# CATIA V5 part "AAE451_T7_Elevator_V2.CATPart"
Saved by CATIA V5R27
Part number: Elevator
Bounding box of the stored display mesh (mm): x 0 to 69.698, y -12.436 to 0.05, z -344.945 to 344.945
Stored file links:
  W:\AAE 451\AAE451_T7_TailAssembly_V2\AAE451_T7_Elevator_V2.CATPart
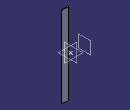
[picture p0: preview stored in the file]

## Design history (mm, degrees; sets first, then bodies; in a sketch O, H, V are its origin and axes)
Set1 "GeometryFromExcel"
  Point1: (1, 0.001, 0)
  Point2: (0.95, 0.0067, 0)
  Point3: (0.9, 0.0121, 0)
  Point4: (0.8, 0.0219, 0)
  Point5: (0.7, 0.0305, 0)
  Point6: (0.6, 0.038, 0)
  Point7: (0.5, 0.0441, 0)
  Point8: (0.4, 0.0484, 0)
  Point9: (0.3, 0.05, 0)
  Point10: (0.25, 0.0495, 0)
  Point11: (0.2, 0.0478, 0)
  Point12: (0.15, 0.0445, 0)
  Point13: (0.1, 0.039, 0)
  Point14: (0.075, 0.035, 0)
  Point15: (0.05, 0.0296, 0)
  Point16: (0.025, 0.0218, 0)
  Point17: (0.0125, 0.0158, 0)
  Point18: (0, 0, 0)
  Point19: (0.0125, -0.0158, 0)
  Point20: (0.025, -0.0218, 0)
  Point21: (0.05, -0.0296, 0)
  Point22: (0.075, -0.035, 0)
  Point23: (0.1, -0.039, 0)
  Point24: (0.15, -0.0445, 0)
  Point25: (0.2, -0.0478, 0)
  Point26: (0.25, -0.0495, 0)
  Point27: (0.3, -0.05, 0)
  Point28: (0.4, -0.0484, 0)
  Point29: (0.5, -0.0441, 0)
  Point30: (0.6, -0.038, 0)
  Point31: (0.7, -0.0305, 0)
  Point32: (0.8, -0.0219, 0)
  Point33: (0.9, -0.0121, 0)
  Point34: (0.95, -0.0067, 0)
  Point35: (1, -0.001, 0)
  Point36: (1, 0.001, 0)
  Point37: (0.95, 0.0067, 0)
  Point38: (0.9, 0.0121, 0)
  Point39: (0.8, 0.0219, 0)
  Point40: (0.7, 0.0305, 0)
  Point41: (0.6, 0.038, 0)
  Point42: (0.5, 0.0441, 0)
  Point43: (0.4, 0.0484, 0)
  Point44: (0.3, 0.05, 0)
  Point45: (0.25, 0.0495, 0)
  Point46: (0.2, 0.0478, 0)
  Point47: (0.15, 0.0445, 0)
  Point48: (0.1, 0.039, 0)
  Point49: (0.075, 0.035, 0)
  Point50: (0.05, 0.0296, 0)
  Point51: (0.025, 0.0218, 0)
  Point52: (0.0125, 0.0158, 0)
  Point53: (0, 0, 0)
  Point54: (0.0125, -0.0158, 0)
  Point55: (0.025, -0.0218, 0)
  Point56: (0.05, -0.0296, 0)
  Point57: (0.075, -0.035, 0)
  Point58: (0.1, -0.039, 0)
  Point59: (0.15, -0.0445, 0)
  Point60: (0.2, -0.0478, 0)
  Point61: (0.25, -0.0495, 0)
  Point62: (0.3, -0.05, 0)
  Point63: (0.4, -0.0484, 0)
  Point64: (0.5, -0.0441, 0)
  Point65: (0.6, -0.038, 0)
  Point66: (0.7, -0.0305, 0)
  Point67: (0.8, -0.0219, 0)
  Point68: (0.9, -0.0121, 0)
  Point69: (0.95, -0.0067, 0)
  Point70: (1, -0.001, 0)
  Curve1: Elements (Point36; Point37; Point38; Point39; Point40; Point41; Point42; Point43; Point44; Point45; Point46; Point47; Point48; Point49; Point50; Point51; Point52; Point53; Point54; Point55; Point56; Point57; Point58; Point59; Point60; Point61; Point62; Point63; Point64; Point65; Point66; Point67; Point68; Point69; Point70)
  Sketch1 on xy-plane, origin (0, 0, 0), H (1, 0, 0), V (0, 1, 0)
    projected curve E1 from edge of Curve1
    point P1 (1, 0.0011)
    line L1 (1, 0.0011) -> (1, -0.001)
    point P3 (1, 0.001)
    point P4 (1, -0.001)
    reference projected point E2 (1, 0.001) from Point1
    reference projected point E3 (1, -0.001) from Point35
    coincidence: P3 E2, P4 E3, P1 P3
Body1 (main body)
  Pad1: profile Sketch1, direction (0, 0, 1), length 1.5215, mirrored extent
  Scaling1: ToTransfor Pad1, Reference Point40, Ratio 230
  Plane1: type Offset, RefPlane yz-plane, Offset 120, reversed
  Sketch2 on xy-plane, origin (0, 0, 0), H (1, 0, 0), V (0, 1, 0)
    reference projected line E1 (69.6979, -7.2245) -> (69.698, -6.7499) from edge [face of Pad1 from Sketch1.L1 | end face of Pad1]
    line L1 (13.6994, -1.0636) -> (13.6965, -12.9194)
    projected curve E2 from edge [face of Pad1 from Sketch1.E1 | end face of Pad1]
    projected curve E3 from edge [face of Pad1 from Sketch1.E1 | end face of Pad1]
    distance E1 L1 = 56
  Pocket1: profile Sketch2, direction (0, 0, -1), through (limit type 3), opposite side through (limit type 3)
  Fillet1: radius 5, on edge [face of Pad1 from Sketch1.E1 | face of Pocket1 from Sketch2.L1]; edge [face of Pocket1 from Sketch2.L1 | face of Pad1 from Sketch1.E1]
  Sketch3 on zx-plane, origin (0, 0, 0), H (-1, 0, 0), V (0, 0, 1)
    line L1 (-135.4649, -344.945) -> (50.2623, -344.945)
    line L2 (50.2623, -344.945) -> (50.2623, -349.945)
    line L3 (50.2623, -349.945) -> (-135.4649, -349.945)
    line L4 (-135.4649, -349.945) -> (-135.4649, -344.945)
    line L5 (-146.4826, 349.945) -> (56.5582, 349.945)
    line L6 (56.5582, 349.945) -> (56.5582, 344.945)
    line L7 (56.5582, 344.945) -> (-146.4826, 344.945)
    line L8 (-146.4826, 344.945) -> (-146.4826, 349.945)
    reference projected line E1 (-69.7, 349.945) -> (160.3, 349.945) from edge [face of Pad1 from Sketch1.E1 | end face of Pad1]
    reference projected line E2 (-69.7, -349.945) -> (160.3, -349.945) from edge [start face of Pad1 | face of Pad1 from Sketch1.E1]
    distance L7 L5 = 5
    horizontal: L1 H, L3 H, L5 H, L7 H
    vertical: L2 V, L4 V, L6 V, L8 V
    coincidence: L5 E1, L3 E2
    symmetry: L7 L1 H
  Pocket2: profile Sketch3, direction (0, -1, 0), through (limit type 3)
  Sketch4 on face of Pocket1 from Sketch2.L1, origin (13.6996, -0.0033, 0), H (-0.0002, -1, 0), V (0, 0, 1)
    line L1 (6.4867, 8) -> (7.4867, 8)
    line L2 (7.4867, 8) -> (7.4867, -8)
    line L3 (7.4867, -8) -> (6.4867, -8)
    line L4 (6.4867, -8) -> (6.4867, 8)
    construction line L5 (6.9867, 7.1913) -> (6.9867, -6.7162)
    reference projected line E1 (1.5418, 344.945) -> (1.5418, -344.945) from edge [face of Pad1 from Sketch1.E1 | face of Fillet1]
    reference projected line E2 (12.4317, 344.945) -> (12.4317, -344.945) from edge [face of Fillet1 | face of Pad1 from Sketch1.E1]
    distance L4 L2 = 1
    distance L1 L3 = 16
    horizontal: L1 H, L3 H
    vertical: L2 V, L4 V
    symmetry: L3 L1 H, L4 L2 L5, E1 E2 L5
  Pocket3: profile Sketch4, direction (1, -0.0002, 0), length 13.7
  RectPattern1: of Pocket3, direction 1 instances 2, spacing 230, along zx-plane
  Mirror1: of RectPattern1, about xy-plane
